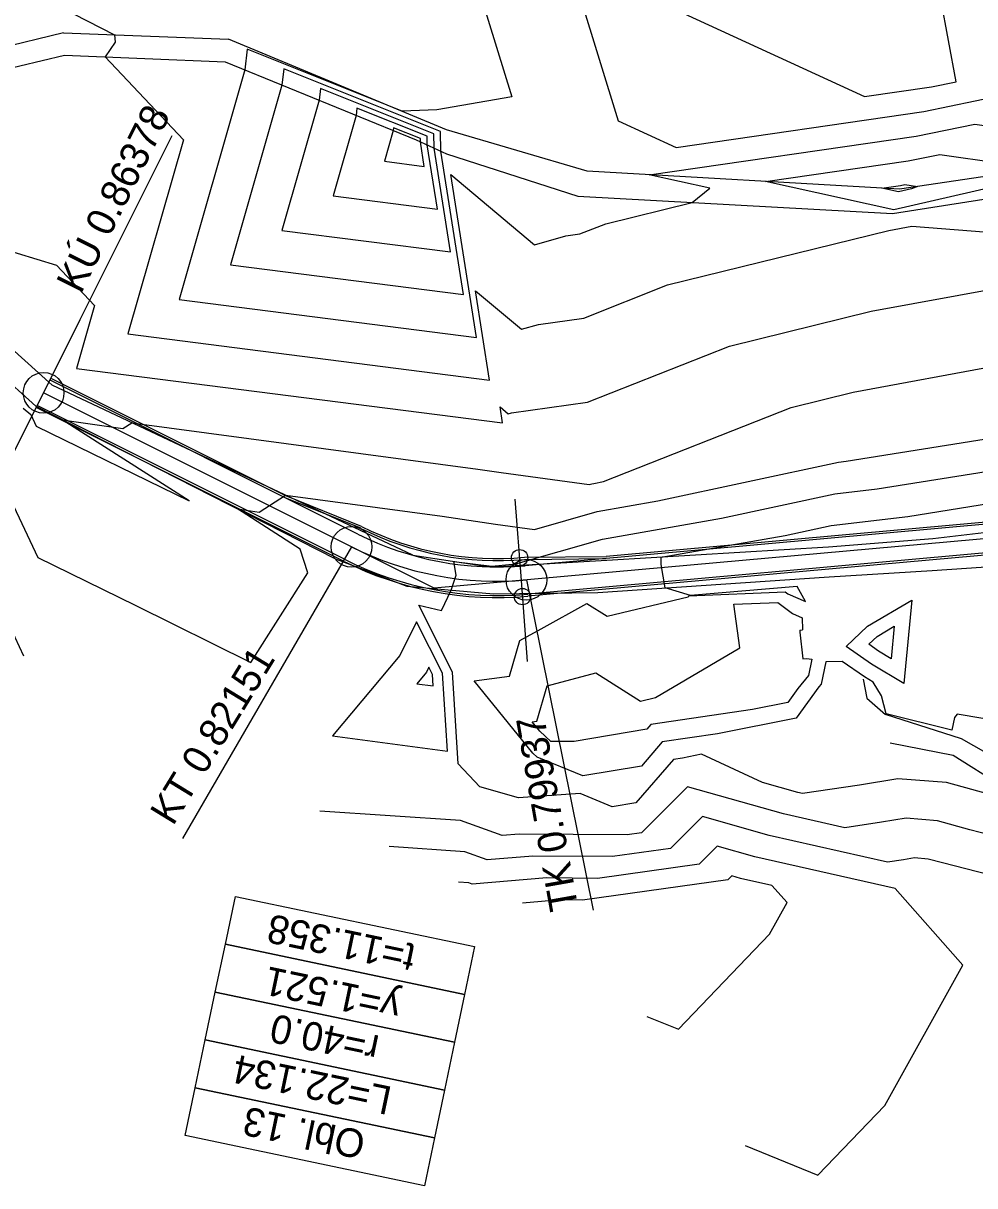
# Model space of a CAD drawing. Extents: x -549394 to -546608, y -1037055 to -1033629.
# Drawn here: x -548402.9 to -548286, y -1035623.5 to -1035480.8 of the extents above; entities that cross this region are included whole.
import ezdxf

# ---------------------------------------------------------------- set-up
doc = ezdxf.new("R2010")
doc.units = 0
for name, color, linetype in [('hlavni_vrst', 7, 'Continuous'), ('hrana_L', 7, 'Continuous'), ('norm_vrst', 7, 'Continuous'), ('POLYGONY_SITUACE_PO', 7, 'Continuous'), ('u_sirka_0_5m', 7, 'Continuous'), ('u_sirka_1_0m', 7, 'Continuous'), ('x_navrh_C11', 7, 'Continuous'), ('x_osa_C11', 7, 'Continuous'), ('x_popis_oblouky_C11', 7, 'Continuous'), ('x_popis_pricne_rezy_C11', 7, 'Continuous')]:
    doc.layers.add(name, color=color, linetype=linetype)

msp = doc.modelspace()

# ---------------------------------------------------------------- linework, layer by layer
at = {"layer": 'hlavni_vrst'}
for p, q in [((-548349.79, -1035467.47), (-548342.87, -1035489.84)), ((-548375.38, -1035484.01), (-548375.68, -1035486.56)), ((-548356.35, -1035491.63), (-548375.38, -1035484.01)), ((-548375.68, -1035486.56), (-548383.73, -1035514.73)), ((-548342.87, -1035489.84), (-548352.09, -1035491.46)), ((-548352.09, -1035491.46), (-548356.35, -1035491.63)), ((-548293.25, -1035494.7), (-548286.05, -1035493.2)), ((-548286.05, -1035493.2), (-548278.38, -1035494.31)), ((-548326.04, -1035499.43), (-548293.25, -1035494.7)), ((-548350.36, -1035499.41), (-548340.11, -1035508.02)), ((-548347.23, -1035519.39), (-548350.36, -1035499.41)), ((-548318.57, -1035501.07), (-548326.04, -1035499.43)), ((-548320.75, -1035502.82), (-548318.57, -1035501.07)), ((-548331.36, -1035505.43), (-548320.75, -1035502.82)), ((-548334.55, -1035506.69), (-548331.36, -1035505.43)), ((-548340.11, -1035508.02), (-548336.27, -1035506.94)), ((-548336.27, -1035506.94), (-548334.55, -1035506.69)), ((-548383.73, -1035514.73), (-548347.23, -1035519.39)), ((-548298.04, -1035537.99), (-548271.8, -1035533.77)), ((-548317.15, -1035541.57), (-548303.23, -1035538.61)), ((-548303.23, -1035538.61), (-548298.04, -1035537.99)), ((-548331.75, -1035544.15), (-548317.15, -1035541.57)), ((-548410.46, -1035542.31), (-548402.83, -1035558.47)), ((-548342.4, -1035547.19), (-548331.75, -1035544.15)), ((-548350.03, -1035546.89), (-548345.35, -1035547.47)), ((-548349.72, -1035548.58), (-548350.03, -1035546.89)), ((-548345.35, -1035547.47), (-548342.4, -1035547.19)), ((-548350.35, -1035550.42), (-548349.72, -1035548.58)), ((-548351.52, -1035552.93), (-548350.35, -1035550.42)), ((-548354.31, -1035552.27), (-548351.52, -1035552.93)), ((-548350.18, -1035560.47), (-548354.31, -1035552.27)), ((-548349.47, -1035571.75), (-548350.18, -1035560.47)), ((-548323.04, -1035571.19), (-548327.66, -1035576.54)), ((-548321.95, -1035571.03), (-548323.04, -1035571.19)), ((-548319.62, -1035570.57), (-548321.95, -1035571.03)), ((-548312.11, -1035574.03), (-548319.62, -1035570.57)), ((-548346.83, -1035574.57), (-548349.47, -1035571.75)), ((-548342.05, -1035575.9), (-548346.83, -1035574.57)), ((-548307.76, -1035575.26), (-548312.11, -1035574.03)), ((-548300.21, -1035574.34), (-548307.2, -1035575.39)), ((-548295.5, -1035573.57), (-548300.21, -1035574.34)), ((-548289.51, -1035574.05), (-548295.5, -1035573.57)), ((-548283.29, -1035575.77), (-548289.51, -1035574.05)), ((-548334.51, -1035575.4), (-548342.05, -1035575.9)), ((-548330.55, -1035577.03), (-548334.51, -1035575.4)), ((-548307.2, -1035575.39), (-548307.76, -1035575.26)), ((-548327.66, -1035576.54), (-548330.55, -1035577.03))]:
    msp.add_line(p, q, dxfattribs=at)
at = {"layer": 'hrana_L'}
for p, q in [((-548397.94, -1035481.98), (-548424.88, -1035488.54)), ((-548397.94, -1035481.98), (-548377.67, -1035482.78)), ((-548350.91, -1035493.89), (-548377.67, -1035482.78)), ((-548424.09, -1035491.03), (-548397.82, -1035484.75)), ((-548397.82, -1035484.75), (-548378.09, -1035485.58)), ((-548378.09, -1035485.58), (-548354.63, -1035495.14)), ((-548333.62, -1035498.99), (-548350.91, -1035493.89)), ((-548354.63, -1035495.14), (-548350.9, -1035496.85)), ((-548350.9, -1035496.85), (-548334.77, -1035502.05)), ((-548434.64, -1035497.68), (-548401.33, -1035527.85)), ((-548428.68, -1035498.83), (-548399.35, -1035525.24)), ((-548275.92, -1035498.32), (-548295.3, -1035501.2)), ((-548295.3, -1035501.2), (-548333.62, -1035498.99)), ((-548296.13, -1035504.17), (-548274.43, -1035500.8)), ((-548334.77, -1035502.05), (-548296.13, -1035504.17)), ((-548355.05, -1035546.14), (-548399.35, -1035525.24)), ((-548401.33, -1035527.85), (-548364.53, -1035546.59)), ((-548264.75, -1035540.94), (-548291.18, -1035544.12)), ((-548291.18, -1035544.12), (-548304, -1035545.14)), ((-548304, -1035545.14), (-548331.23, -1035546.79)), ((-548364.53, -1035546.59), (-548355.78, -1035549.93)), ((-548355.05, -1035546.14), (-548345.31, -1035547.6)), ((-548331.23, -1035546.79), (-548345.31, -1035547.6)), ((-548291.26, -1035548), (-548263.97, -1035546.13)), ((-548332.34, -1035550.7), (-548303.93, -1035548.8)), ((-548303.93, -1035548.8), (-548291.26, -1035548)), ((-548355.78, -1035549.93), (-548345.16, -1035550.89)), ((-548345.16, -1035550.89), (-548332.34, -1035550.7)), ((-548299.75, -1035561.36), (-548299.29, -1035563.67)), ((-548299.29, -1035563.67), (-548297.01, -1035565.68)), ((-548287.66, -1035568.68), (-548297.01, -1035565.68)), ((-548280.93, -1035572.5), (-548287.66, -1035568.68)), ((-548296.43, -1035569.15), (-548288.7, -1035570.68)), ((-548288.7, -1035570.68), (-548282.38, -1035574.67))]:
    msp.add_line(p, q, dxfattribs=at)
at = {"layer": 'norm_vrst'}
for p, q in [((-548338.61, -1035464.39), (-548329.83, -1035492.8)), ((-548288.31, -1035488.02), (-548290.21, -1035477.82)), ((-548396.7, -1035479.67), (-548391.66, -1035482.23)), ((-548321.77, -1035479.64), (-548299.57, -1035489.83)), ((-548391.61, -1035483.13), (-548392.81, -1035484.96)), ((-548391.66, -1035482.23), (-548391.61, -1035483.13)), ((-548392.81, -1035484.96), (-548383.21, -1035495.14)), ((-548370.89, -1035486.42), (-548371.12, -1035488.42)), ((-548351.63, -1035494.13), (-548370.89, -1035486.42)), ((-548371.12, -1035488.42), (-548377.43, -1035510.49)), ((-548366.4, -1035488.83), (-548366.56, -1035490.28)), ((-548352.46, -1035494.41), (-548366.4, -1035488.83)), ((-548299.57, -1035489.83), (-548291.35, -1035488.65)), ((-548291.35, -1035488.65), (-548288.31, -1035488.02)), ((-548366.56, -1035490.28), (-548371.13, -1035506.25)), ((-548292.3, -1035491.67), (-548281.75, -1035489.47)), ((-548361.91, -1035491.24), (-548362.01, -1035492.13)), ((-548353.29, -1035494.69), (-548361.91, -1035491.24)), ((-548322.73, -1035496.06), (-548292.3, -1035491.67)), ((-548362.01, -1035492.13), (-548364.83, -1035502.01)), ((-548329.83, -1035492.8), (-548322.73, -1035496.06)), ((-548357.45, -1035493.99), (-548358.54, -1035497.77)), ((-548357.41, -1035493.65), (-548357.45, -1035493.99)), ((-548354.12, -1035494.97), (-548357.41, -1035493.65)), ((-548352.43, -1035496.15), (-548352.46, -1035494.41)), ((-548351.59, -1035496.53), (-548351.63, -1035494.13)), ((-548383.21, -1035495.14), (-548390.03, -1035518.97)), ((-548354.11, -1035495.38), (-548354.12, -1035494.97)), ((-548353.64, -1035498.39), (-548354.11, -1035495.38)), ((-548353.27, -1035495.76), (-548353.29, -1035494.69)), ((-548352.03, -1035503.64), (-548353.27, -1035495.76)), ((-548350.43, -1035508.89), (-548352.43, -1035496.15)), ((-548348.83, -1035514.14), (-548351.59, -1035496.53)), ((-548294.21, -1035497.72), (-548290.35, -1035496.92)), ((-548290.35, -1035496.92), (-548278.29, -1035498.67)), ((-548358.54, -1035497.77), (-548353.64, -1035498.39)), ((-548311.74, -1035500.25), (-548294.21, -1035497.72)), ((-548296, -1035503.71), (-548311.74, -1035500.25)), ((-548297.44, -1035501.08), (-548295.16, -1035500.75)), ((-548295.39, -1035501.53), (-548297.44, -1035501.08)), ((-548284.03, -1035500.98), (-548296, -1035503.71)), ((-548293.83, -1035501.17), (-548295.39, -1035501.53)), ((-548295.16, -1035500.75), (-548294.65, -1035500.64)), ((-548294.65, -1035500.64), (-548293.08, -1035500.87)), ((-548293.08, -1035500.87), (-548293.83, -1035501.17)), ((-548364.83, -1035502.01), (-548352.03, -1035503.64)), ((-548296.59, -1035506.26), (-548293.78, -1035505.74)), ((-548293.78, -1035505.74), (-548271.01, -1035507.52)), ((-548413.16, -1035506.15), (-548398.79, -1035510.52)), ((-548371.13, -1035506.25), (-548350.43, -1035508.89)), ((-548323.77, -1035512.95), (-548296.59, -1035506.26)), ((-548398.79, -1035510.52), (-548394.12, -1035515.48)), ((-548377.43, -1035510.49), (-548348.83, -1035514.14)), ((-548334.06, -1035517.01), (-548323.77, -1035512.95)), ((-548298.78, -1035516.19), (-548282.59, -1035513.2)), ((-548347.35, -1035513.66), (-548341.71, -1035518.39)), ((-548345.62, -1035524.64), (-548347.35, -1035513.66)), ((-548394.12, -1035515.48), (-548396.33, -1035523.21)), ((-548339.6, -1035517.79), (-548334.06, -1035517.01)), ((-548316.18, -1035520.47), (-548298.78, -1035516.19)), ((-548341.71, -1035518.39), (-548339.6, -1035517.79)), ((-548390.03, -1035518.97), (-548345.62, -1035524.64)), ((-548333.58, -1035527.33), (-548316.18, -1035520.47)), ((-548300.96, -1035526.11), (-548271.41, -1035520.66)), ((-548396.33, -1035523.21), (-548344.02, -1035529.89)), ((-548342.94, -1035528.65), (-548333.58, -1035527.33)), ((-548308.59, -1035527.99), (-548300.96, -1035526.11)), ((-548402.88, -1035528.06), (-548401.97, -1035528.86)), ((-548401.97, -1035528.86), (-548401.3, -1035530.27)), ((-548344.33, -1035527.91), (-548343.32, -1035528.76)), ((-548344.02, -1035529.89), (-548344.33, -1035527.91)), ((-548343.32, -1035528.76), (-548342.94, -1035528.65)), ((-548331.63, -1035537.08), (-548308.59, -1035527.99)), ((-548301.84, -1035534.6), (-548261.1, -1035528.06)), ((-548401.3, -1035530.27), (-548382.51, -1035539.45)), ((-548382.51, -1035539.45), (-548398.1, -1035529.49)), ((-548398.1, -1035529.49), (-548390.65, -1035530.58)), ((-548390.65, -1035530.58), (-548389.55, -1035529.86)), ((-548389.55, -1035529.86), (-548347.07, -1035535.55)), ((-548302.77, -1035534.72), (-548301.84, -1035534.6)), ((-548406.21, -1035535.58), (-548401.1, -1035546.42)), ((-548347.07, -1035535.55), (-548344.2, -1035535.97)), ((-548344.2, -1035535.97), (-548333.38, -1035537.46)), ((-548324.97, -1035539.45), (-548302.77, -1035534.72)), ((-548333.38, -1035537.46), (-548333.08, -1035537.38)), ((-548333.08, -1035537.38), (-548332.8, -1035537.32)), ((-548332.8, -1035537.32), (-548331.63, -1035537.08)), ((-548373.9, -1035540.84), (-548370.7, -1035538.76)), ((-548370.7, -1035538.76), (-548351.43, -1035541.34)), ((-548332.42, -1035540.76), (-548324.97, -1035539.45)), ((-548294.25, -1035541.38), (-548282.51, -1035539.49)), ((-548368.87, -1035545.38), (-548376.58, -1035540.45)), ((-548376.58, -1035540.45), (-548373.9, -1035540.84)), ((-548351.43, -1035541.34), (-548344.88, -1035542.3)), ((-548340.1, -1035542.96), (-548332.42, -1035540.76)), ((-548303.69, -1035542.5), (-548294.25, -1035541.38)), ((-548344.88, -1035542.3), (-548340.1, -1035542.96)), ((-548309.32, -1035543.7), (-548303.69, -1035542.5)), ((-548324.57, -1035546.39), (-548309.32, -1035543.7)), ((-548367.93, -1035548.31), (-548368.87, -1035545.38)), ((-548401.1, -1035546.42), (-548389.12, -1035552.27)), ((-548324.56, -1035547.28), (-548324.57, -1035546.39)), ((-548324.05, -1035550.15), (-548324.56, -1035547.28)), ((-548374.94, -1035559.31), (-548367.93, -1035548.31)), ((-548320.96, -1035551.07), (-548324.05, -1035550.15)), ((-548307.86, -1035549.98), (-548320.96, -1035551.07)), ((-548306.82, -1035551.8), (-548307.86, -1035549.98)), ((-548331.19, -1035553.62), (-548321.25, -1035551.22)), ((-548321.25, -1035551.22), (-548321.15, -1035551.16)), ((-548321.15, -1035551.11), (-548309.32, -1035550.64)), ((-548321.15, -1035551.16), (-548321.15, -1035551.11)), ((-548309.32, -1035550.64), (-548309, -1035550.89)), ((-548309, -1035550.89), (-548306.82, -1035551.8)), ((-548299.21, -1035554.83), (-548293.79, -1035551.63)), ((-548293.79, -1035551.63), (-548294.77, -1035561.88)), ((-548389.12, -1035552.27), (-548374.94, -1035559.31)), ((-548339.28, -1035555.15), (-548333.68, -1035552.05)), ((-548333.68, -1035552.05), (-548331.19, -1035553.62)), ((-548315.64, -1035552.13), (-548310.21, -1035551.92)), ((-548314.91, -1035557.52), (-548315.64, -1035552.13)), ((-548310.21, -1035551.92), (-548308.42, -1035553.3)), ((-548354.6, -1035554.29), (-548356.65, -1035558.44)), ((-548351.39, -1035560.63), (-548354.6, -1035554.29)), ((-548308.42, -1035553.3), (-548307.23, -1035553.8)), ((-548307.23, -1035553.8), (-548307.2, -1035555.29)), ((-548341.9, -1035556.62), (-548339.28, -1035555.15)), ((-548307.54, -1035555.32), (-548307.2, -1035555.29)), ((-548307.54, -1035555.32), (-548307.53, -1035555.57)), ((-548307.53, -1035555.57), (-548307.15, -1035558.85)), ((-548301.83, -1035557.32), (-548299.21, -1035554.83)), ((-548298.05, -1035556.1), (-548295.93, -1035554.85)), ((-548295.93, -1035554.85), (-548296.31, -1035558.85)), ((-548343.19, -1035560.97), (-548341.9, -1035556.62)), ((-548298.72, -1035559.49), (-548301.83, -1035557.32)), ((-548299.07, -1035557.07), (-548298.05, -1035556.1)), ((-548297.85, -1035557.92), (-548299.07, -1035557.07)), ((-548356.65, -1035558.44), (-548364.89, -1035568.3)), ((-548325.23, -1035563.59), (-548314.91, -1035557.52)), ((-548307.15, -1035558.85), (-548306.72, -1035558.81)), ((-548306.72, -1035558.81), (-548306.04, -1035558.9)), ((-548296.31, -1035558.85), (-548297.85, -1035557.92)), ((-548353.08, -1035559.87), (-548353.38, -1035560.47)), ((-548352.61, -1035560.79), (-548353.08, -1035559.87)), ((-548306.04, -1035558.9), (-548306.47, -1035560.91)), ((-548304.32, -1035559.22), (-548304.92, -1035561.97)), ((-548302.32, -1035559.16), (-548304.32, -1035559.22)), ((-548299.59, -1035561.06), (-548302.32, -1035559.16)), ((-548294.77, -1035561.88), (-548298.72, -1035559.49)), ((-548353.38, -1035560.47), (-548354.57, -1035561.91)), ((-548352.53, -1035562.18), (-548352.61, -1035560.79)), ((-548350.8, -1035570.19), (-548351.39, -1035560.63)), ((-548347.53, -1035561.56), (-548343.19, -1035560.97)), ((-548340.31, -1035570.43), (-548347.53, -1035561.56)), ((-548338.53, -1035562.18), (-548332.57, -1035560.57)), ((-548332.57, -1035560.57), (-548327.09, -1035564.03)), ((-548306.47, -1035560.91), (-548307.76, -1035562.5)), ((-548298.54, -1035561.7), (-548299.59, -1035561.06)), ((-548297.5, -1035563.39), (-548298.54, -1035561.7)), ((-548354.57, -1035561.91), (-548352.53, -1035562.18)), ((-548339.82, -1035566.51), (-548338.53, -1035562.18)), ((-548307.76, -1035562.5), (-548309.01, -1035564.22)), ((-548305.18, -1035562.28), (-548307.96, -1035566.13)), ((-548304.92, -1035561.97), (-548305.18, -1035562.28)), ((-548327.09, -1035564.03), (-548325.23, -1035563.59)), ((-548309.01, -1035564.22), (-548313.35, -1035565.08)), ((-548296.93, -1035565.6), (-548297.5, -1035563.39)), ((-548313.35, -1035565.08), (-548325.83, -1035566.92)), ((-548288.87, -1035567.62), (-548296.93, -1035565.6)), ((-548288.19, -1035565.64), (-548288.53, -1035566.05)), ((-548285.05, -1035566.19), (-548288.19, -1035565.64)), ((-548340.38, -1035566.59), (-548339.82, -1035566.51)), ((-548339.44, -1035567.74), (-548340.38, -1035566.59)), ((-548325.83, -1035566.92), (-548326.31, -1035567.47)), ((-548307.96, -1035566.13), (-548317.65, -1035568.06)), ((-548288.53, -1035566.05), (-548288.87, -1035567.62)), ((-548364.89, -1035568.3), (-548350.8, -1035570.19)), ((-548338.1, -1035568.99), (-548339.44, -1035567.74)), ((-548326.31, -1035567.47), (-548335.24, -1035568.98)), ((-548317.65, -1035568.06), (-548324.43, -1035569.06)), ((-548335.24, -1035568.98), (-548338.1, -1035568.99)), ((-548324.43, -1035569.06), (-548326.98, -1035572.01)), ((-548339.79, -1035570.92), (-548340.31, -1035570.43)), ((-548334.19, -1035573.23), (-548339.79, -1035570.92)), ((-548326.98, -1035572.01), (-548334.19, -1035573.23)), ((-548321.3, -1035574.56), (-548326.95, -1035580.22)), ((-548309.53, -1035577.89), (-548321.3, -1035574.56)), ((-548349.18, -1035578.71), (-548366.45, -1035577.55)), ((-548344.06, -1035580.54), (-548349.18, -1035578.71)), ((-548319.49, -1035578.2), (-548323.42, -1035582.14)), ((-548311.29, -1035580.53), (-548319.49, -1035578.2)), ((-548301.98, -1035579.6), (-548309.53, -1035577.89)), ((-548294.47, -1035578.43), (-548297.49, -1035578.92)), ((-548290.63, -1035578.74), (-548294.47, -1035578.43)), ((-548286.64, -1035579.84), (-548290.63, -1035578.74)), ((-548326.95, -1035580.22), (-548328.71, -1035580.46)), ((-548297.49, -1035578.92), (-548301.98, -1035579.6)), ((-548276.78, -1035582.39), (-548286.64, -1035579.84)), ((-548341.97, -1035580.37), (-548344.06, -1035580.54)), ((-548328.71, -1035580.46), (-548341.97, -1035580.37)), ((-548296.76, -1035583.8), (-548311.29, -1035580.53)), ((-548348.67, -1035582.54), (-548357.94, -1035581.91)), ((-548345.92, -1035583.52), (-548348.67, -1035582.54)), ((-548340.29, -1035583.06), (-548345.92, -1035583.52)), ((-548330.54, -1035583.13), (-548340.29, -1035583.06)), ((-548323.42, -1035582.14), (-548330.54, -1035583.13)), ((-548317.68, -1035581.85), (-548319.89, -1035584.07)), ((-548313.06, -1035583.16), (-548317.68, -1035581.85)), ((-548319.89, -1035584.07), (-548332.37, -1035585.8)), ((-548295.82, -1035587.05), (-548313.06, -1035583.16)), ((-548294.78, -1035583.51), (-548296.76, -1035583.8)), ((-548293.45, -1035583.29), (-548294.78, -1035583.51)), ((-548291.75, -1035583.43), (-548293.45, -1035583.29)), ((-548289.99, -1035583.91), (-548291.75, -1035583.43)), ((-548272.37, -1035588.47), (-548289.99, -1035583.91)), ((-548338.6, -1035585.75), (-548347.77, -1035586.5)), ((-548332.37, -1035585.8), (-548338.6, -1035585.75)), ((-548315.87, -1035585.5), (-548316.36, -1035586)), ((-548314.83, -1035585.8), (-548315.87, -1035585.5)), ((-548310.95, -1035586.67), (-548314.83, -1035585.8)), ((-548348.15, -1035586.37), (-548349.43, -1035586.28)), ((-548347.77, -1035586.5), (-548348.15, -1035586.37)), ((-548316.36, -1035586), (-548334.2, -1035588.47)), ((-548309.09, -1035588.78), (-548310.95, -1035586.67)), ((-548287.53, -1035596.44), (-548295.82, -1035587.05)), ((-548336.91, -1035588.45), (-548341.57, -1035588.83)), ((-548334.2, -1035588.47), (-548336.91, -1035588.45)), ((-548311.23, -1035592.66), (-548309.09, -1035588.78)), ((-548322.43, -1035604.32), (-548311.23, -1035592.66)), ((-548297.08, -1035613.68), (-548287.53, -1035596.44)), ((-548326.3, -1035602.74), (-548322.43, -1035604.32)), ((-548305.3, -1035622.25), (-548297.08, -1035613.68)), ((-548314.22, -1035618.61), (-548305.3, -1035622.25))]:
    msp.add_line(p, q, dxfattribs=at)
at = {"layer": 'POLYGONY_SITUACE_PO'}
for centre in [(-548400.38, -1035526.2), (-548362.57, -1035545.1), (-548341.1, -1035549.16)]:
    msp.add_circle(centre, 2.5, dxfattribs=at)
at = {"layer": 'u_sirka_0_5m'}
msp.add_circle((-548400.38, -1035526.2), 2.5, dxfattribs=at)
at = {"layer": 'u_sirka_1_0m'}
for centre in [(-548341.93, -1035546.43), (-548341.58, -1035551.21)]:
    msp.add_circle(centre, 1, dxfattribs=at)
at = {"layer": 'x_navrh_C11'}
for p, q in [((-548370.63, -1035538.84), (-548399.37, -1035524.47)), ((-548361.79, -1035543.54), (-548399.49, -1035524.69)), ((-548363.46, -1035546.89), (-548401.28, -1035527.99)), ((-548363.35, -1035546.67), (-548401.16, -1035527.76)), ((-548361.33, -1035542.6), (-548370.63, -1035538.84)), ((-548361.43, -1035542.83), (-548370.73, -1035539.07)), ((-548272.87, -1035541.27), (-548341.25, -1035547.42)), ((-548272.56, -1035544.76), (-548340.94, -1035550.91)), ((-548341.34, -1035546.39), (-548331.31, -1035546.28)), ((-548341.33, -1035546.64), (-548331.3, -1035546.53))]:
    msp.add_line(p, q, dxfattribs=at)
for points in [[(-548272.9, -1035541.02), (-548331.31, -1035546.28)], [(-548282.5, -1035545.9), (-548340.92, -1035551.16)]]:
    msp.add_lwpolyline(points, dxfattribs=at)
for radius, start, end in [(37.46, 243.4359, 275.1399), (37.21, 243.4207, 275.1551), (38.25, 243.4359, 275.1399), (42, 243.4359, 275.1399), (41.75, 243.4359, 275.1399)]:
    msp.add_arc((-548344.68, -1035509.33), radius, start, end, dxfattribs=at)
at = {"layer": 'x_osa_C11'}
for points in [[(-548352.41, -1035550.18), (-548400.38, -1035526.2)], [(-548226.33, -1035545.48), (-548263.92, -1035542.22), (-548352.41, -1035550.18)]]:
    msp.add_lwpolyline(points, dxfattribs=at)
msp.add_arc((-548344.68, -1035509.33), 40, 243.4359, 275.1399, dxfattribs=at)
at = {"layer": 'x_popis_oblouky_C11'}
for points in [[(-548400.38, -1035526.2), (-548384.58, -1035494.59)], [(-548362.57, -1035545.1), (-548383.32, -1035580.9)], [(-548341.1, -1035549.16), (-548332.9, -1035589.72)]]:
    msp.add_lwpolyline(points, dxfattribs=at)
for points in [[(-548348.7, -1035600.05), (-548378.06, -1035593.88), (-548376.83, -1035588.01), (-548347.47, -1035594.18)], [(-548349.94, -1035605.92), (-548379.3, -1035599.76), (-548378.06, -1035593.88), (-548348.7, -1035600.05)], [(-548351.17, -1035611.79), (-548380.53, -1035605.63), (-548379.3, -1035599.76), (-548349.94, -1035605.92)], [(-548352.4, -1035617.67), (-548381.76, -1035611.5), (-548380.53, -1035605.63), (-548351.17, -1035611.79)], [(-548353.63, -1035623.54), (-548382.99, -1035617.37), (-548381.76, -1035611.5), (-548352.4, -1035617.67)]]:
    msp.add_lwpolyline(points, close=True, dxfattribs=at)
at = {"layer": 'x_popis_pricne_rezy_C11'}
for points in [[(-548404.85, -1035535.14), (-548400.38, -1035526.2), (-548395.91, -1035517.25)], [(-548340.98, -1035559.19), (-548341.72, -1035549.22), (-548342.46, -1035539.24)]]:
    msp.add_lwpolyline(points, dxfattribs=at)

# ---------------------------------------------------------------- texts
at = {"layer": 'x_popis_oblouky_C11'}
for s, rotation, p in [('KÚ 0.86378', 63.4359, (-548395.8, -1035514.15)), ('KT 0.82151', 58.526, (-548384.49, -1035579.46)), ('TK 0.79937', 100.06, (-548334.72, -1035589.46)), ('t=11.358', 168.1626, (-548354.51, -1035593.93)), ('y=1.521', 168.1626, (-548356.35, -1035600.04)), ('r=40.0', 168.1626, (-548358.98, -1035605.16)), ('L=22.134', 168.1626, (-548357.44, -1035611.44)), ('Obl. 13', 168.1626, (-548360.67, -1035616.9))]:
    msp.add_text(s, height=3.5, rotation=rotation, dxfattribs=at).set_placement(p)

doc.saveas('drawing.dxf')
